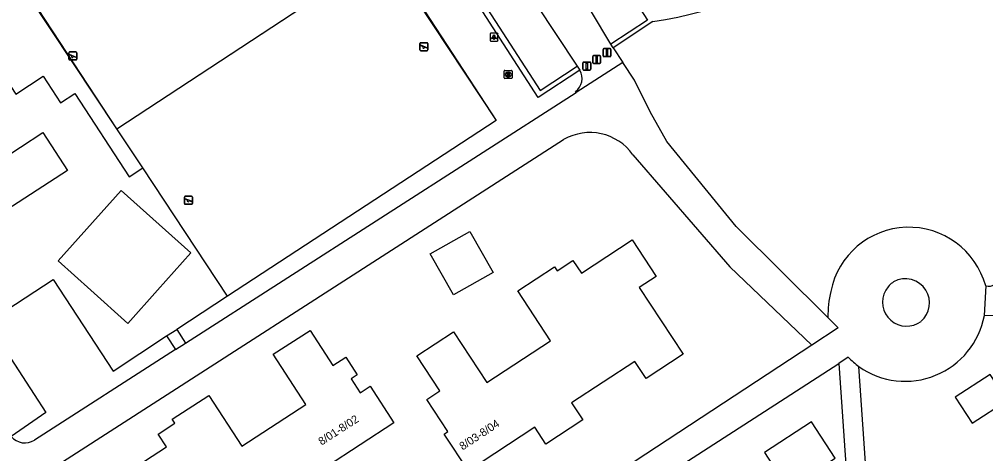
# Model space of a CAD drawing. Extents: x 159451 to 160663, y 388402 to 389723.
# Drawn here: x 159974 to 160094.7, y 389229.6 to 389283.8 of the extents above; entities that cross this region are included whole.
import ezdxf

# ---------------------------------------------------------------- set-up
doc = ezdxf.new("R2010")
doc.units = 0
for name, color, linetype in [('IMGEO_Afsluitpaal', 7, 'Continuous'), ('IMGEO_Groenvoorziening', 7, 'Continuous'), ('IMGEO_Haag', 7, 'Continuous'), ('IMGEO_Hek', 7, 'Continuous'), ('IMGEO_Lichtpunt', 7, 'Continuous'), ('IMGEO_Open_loods', 7, 'Continuous'), ('IMGEO_Pand', 7, 'Continuous'), ('IMGEO_Pand_nummerreeks', 7, 'Continuous'), ('IMGEO_Parkeervlak_open', 7, 'Continuous'), ('IMGEO_Rijbaan_lokaal_gesloten', 7, 'Continuous'), ('IMGEO_Rijbaan_lokaal_open', 7, 'Continuous'), ('IMGEO_Rioolput', 7, 'Continuous'), ('IMGEO_Speelvoorziening', 7, 'Continuous'), ('IMGEO_Voetpad_gesloten', 7, 'Continuous'), ('IMGEO_Voetpad_open', 7, 'Continuous')]:
    doc.layers.add(name, color=color, linetype=linetype)

msp = doc.modelspace()

# ---------------------------------------------------------------- linework, layer by layer
at = {"layer": 'IMGEO_Afsluitpaal'}
for p, q in [((160046.91, 389279.29), (160046.91, 389280.09)), ((160046.91, 389280.09), (160046.91, 389279.29)), ((160047.01, 389280.19), (160047.8, 389280.19)), ((160047.8, 389280.19), (160047.01, 389280.19)), ((160047.9, 389280.09), (160047.9, 389279.29)), ((160047.9, 389279.29), (160047.9, 389280.09)), ((160044.39, 389277.61), (160044.39, 389278.41)), ((160044.39, 389278.41), (160044.39, 389277.61)), ((160044.49, 389278.51), (160045.28, 389278.51)), ((160045.28, 389278.51), (160044.49, 389278.51)), ((160045.38, 389278.41), (160045.38, 389277.61)), ((160045.38, 389277.61), (160045.38, 389278.41)), ((160045.62, 389278.43), (160045.62, 389279.22)), ((160045.62, 389279.22), (160045.62, 389278.43)), ((160045.72, 389279.32), (160046.51, 389279.32)), ((160046.51, 389279.32), (160045.72, 389279.32)), ((160046.51, 389278.33), (160045.72, 389278.33)), ((160045.72, 389278.33), (160046.51, 389278.33)), ((160046.61, 389279.22), (160046.61, 389278.43)), ((160046.61, 389278.43), (160046.61, 389279.22)), ((160047.8, 389279.19), (160047.01, 389279.19)), ((160047.01, 389279.19), (160047.8, 389279.19)), ((160045.28, 389277.51), (160044.49, 389277.51)), ((160044.49, 389277.51), (160045.28, 389277.51))]:
    msp.add_line(p, q, dxfattribs=at)
for points in [[(160047.33, 389280.06), (160047.48, 389280.06), (160047.48, 389279.31), (160047.33, 389279.31), (160047.33, 389280.06)], [(160044.81, 389278.38), (160044.96, 389278.38), (160044.96, 389277.63), (160044.81, 389277.63), (160044.81, 389278.38)], [(160046.04, 389279.2), (160046.19, 389279.2), (160046.19, 389278.45), (160046.04, 389278.45), (160046.04, 389279.2)]]:
    msp.add_lwpolyline(points, dxfattribs=at)
for centre, start, end in [((160047.01, 389280.09), 90, 180), ((160047.01, 389280.09), 90, 180), ((160047.8, 389280.09), 0, 90), ((160047.8, 389280.09), 360, 90), ((160044.49, 389278.41), 90, 180), ((160044.49, 389278.41), 90, 180), ((160045.28, 389278.41), 0, 90), ((160045.28, 389278.41), 360, 90), ((160045.72, 389279.22), 90, 180), ((160045.72, 389279.22), 90, 180), ((160045.72, 389278.43), 180, 270), ((160045.72, 389278.43), 180, 270), ((160046.51, 389279.22), 0, 90), ((160046.51, 389279.22), 360, 90), ((160046.51, 389278.43), 270, 0), ((160046.51, 389278.43), 270, 0), ((160047.01, 389279.29), 180, 270), ((160047.01, 389279.29), 180, 270), ((160047.8, 389279.29), 270, 0), ((160047.8, 389279.29), 270, 0), ((160044.49, 389277.61), 180, 270), ((160044.49, 389277.61), 180, 270), ((160045.28, 389277.61), 270, 0), ((160045.28, 389277.61), 270, 0)]:
    msp.add_arc(centre, 0.1, start, end, dxfattribs=at)
at = {"layer": 'IMGEO_Groenvoorziening'}
for points in [[(159986.18, 389270.18), (159974.59, 389287.89), (160008.08, 389309.69), (160019.69, 389292.19)], [(159986.18, 389270.18), (160019.69, 389292.19)], [(160019.69, 389292.19), (160033.58, 389271.21), (160000.03, 389249.27)], [(159989.42, 389265.29), (159986.18, 389270.18)], [(160090.89, 389236.66), (160093.01, 389233.4), (160097.37, 389236.23), (160095.26, 389239.49), (160090.89, 389236.66)], [(160070.01, 389225.22), (160075.89, 389229.04), (160072.95, 389233.56), (160067.07, 389229.74), (160070.01, 389225.22)]]:
    msp.add_lwpolyline(points, dxfattribs=at)
at = {"layer": 'IMGEO_Haag'}
for points in [[(160044.02, 389277.48), (160038.8, 389274.1), (160012.9, 389314.21), (160017.65, 389317.31)], [(160053.14, 389283.56), (160048.18, 389280.3)]]:
    msp.add_lwpolyline(points, dxfattribs=at)
msp.add_arc((160045.07, 389336.91), 53.95, 278.6038, 331.4356, dxfattribs=at)
at = {"layer": 'IMGEO_Hek'}
for points in [[(159986.18, 389270.18), (159975.2, 389286.77), (160008.96, 389308.85), (160019.81, 389292.27)], [(159986.18, 389270.18), (160019.81, 389292.27)], [(160019.81, 389292.27), (160033.58, 389271.21), (160000.03, 389249.27)], [(159989.42, 389265.29), (159986.18, 389270.18)], [(160000.03, 389249.27), (159989.42, 389265.29)]]:
    msp.add_lwpolyline(points, dxfattribs=at)
at = {"layer": 'IMGEO_Lichtpunt'}
for p, q in [((160032.8, 389282.03), (160032.8, 389281.22)), ((160032.8, 389282.03), (160032.8, 389281.22)), ((160033.7, 389282.12), (160032.89, 389282.12)), ((160033.7, 389282.12), (160032.89, 389282.12)), ((160033.79, 389281.22), (160033.79, 389282.03)), ((160033.79, 389281.22), (160033.79, 389282.03)), ((160032.89, 389281.13), (160033.7, 389281.13)), ((160032.89, 389281.13), (160033.7, 389281.13))]:
    msp.add_line(p, q, dxfattribs=at)
for points in [[(160033.17, 389281.69), (160033.21, 389281.67), (160033.02, 389281.4), (160032.98, 389281.43), (160033.17, 389281.69)], [(160033.27, 389281.65), (160033.32, 389281.65), (160033.32, 389281.32), (160033.27, 389281.32), (160033.27, 389281.65)], [(160033.38, 389281.67), (160033.42, 389281.69), (160033.61, 389281.43), (160033.57, 389281.4), (160033.38, 389281.67)]]:
    msp.add_lwpolyline(points, dxfattribs=at)
msp.add_circle((160033.3, 389281.83), 0.0994, dxfattribs=at)
for centre, start, end in [((160032.89, 389282.03), 90, 180), ((160032.89, 389282.03), 90, 180), ((160033.7, 389282.03), 0, 90), ((160033.7, 389282.03), 0, 90), ((160032.89, 389281.22), 180, 270), ((160032.89, 389281.22), 180, 270), ((160033.7, 389281.22), 270, 0), ((160033.7, 389281.22), 270, 360)]:
    msp.add_arc(centre, 0.0946, start, end, dxfattribs=at)
at = {"layer": 'IMGEO_Open_loods'}
msp.add_lwpolyline([(159986.73, 389262.47), (159995.45, 389254.67), (159991.27, 389250), (159987.58, 389245.86), (159982.95, 389250), (159978.86, 389253.66), (159986.73, 389262.47)], dxfattribs=at)
at = {"layer": 'IMGEO_Pand'}
for points in [[(159968.55, 389264.2), (159976.93, 389269.69), (159980.01, 389264.98), (159971.62, 389259.5)], [(160028.25, 389249.43), (160025.34, 389254.56), (160030.26, 389257.35), (160033.17, 389252.23), (160028.25, 389249.43)], [(160051.44, 389250.36), (160056.92, 389242.01), (160052.29, 389238.96), (160050.87, 389241.12), (160042.98, 389235.94), (160044.38, 389233.81), (160039.78, 389230.79), (160038.4, 389232.89), (160030.09, 389227.43), (160027.07, 389232.03), (160027.53, 389232.34), (160024.89, 389236.34), (160026.55, 389237.42), (160023.67, 389241.8), (160028.24, 389244.79), (160032.39, 389238.47), (160040.35, 389243.69), (160036.26, 389249.91), (160040.87, 389252.94), (160041.2, 389252.44), (160043.16, 389253.73), (160044.21, 389252.13), (160050.55, 389256.29), (160053.54, 389251.73), (160051.44, 389250.36)], [(159986.07, 389226.32), (159992.41, 389230.43), (159991.37, 389232.03), (159993.45, 389233.38), (159993.11, 389233.9), (159997.69, 389236.87), (160001.8, 389230.53), (160009.8, 389235.72), (160005.72, 389242.01), (160010.32, 389244.99), (160013.16, 389240.62), (160014.77, 389241.66), (160016.22, 389239.43), (160015.44, 389238.93), (160016.56, 389237.2), (160017.81, 389238.01), (160020.79, 389233.42), (160012.36, 389227.95)]]:
    msp.add_lwpolyline(points, dxfattribs=at)
at = {"layer": 'IMGEO_Parkeervlak_open'}
for points in [[(160017.94, 389316.86), (160013.73, 389314.09), (160039.05, 389274.95), (160043.7, 389278)], [(160044.94, 389295.4), (160052.48, 389283.74), (160047.89, 389280.74)], [(159969.99, 389245.96), (159977.33, 389234.74), (159973, 389231.74)]]:
    msp.add_lwpolyline(points, dxfattribs=at)
at = {"layer": 'IMGEO_Rijbaan_lokaal_gesloten'}
for points in [[(160049.4, 389278.45), (160043.54, 389274.71)], [(160075, 389246.59), (160063.52, 389257.98), (160054.86, 389268.6), (160052.78, 389272.29), (160050.84, 389276.24), (160049.4, 389278.45)], [(159994.77, 389243.39), (160043.54, 389274.71)], [(159966.74, 389220.55), (159969.19, 389222.03), (160041.99, 389268.82)], [(160050.65, 389266.93), (160062.76, 389252.92), (160072.99, 389243.15)], [(160075, 389246.59), (160076.29, 389245.32), (160072.99, 389243.15)], [(159993.51, 389242.58), (159994.77, 389243.39)], [(159993.51, 389242.58), (159975.92, 389231.28)]]:
    msp.add_lwpolyline(points, dxfattribs=at)
for centre, radius, start, end in [((160045.28, 389263.1), 6.6, 35.5165, 119.9336), ((159974.72, 389233.15), 2.22, 219.254, 302.7061)]:
    msp.add_arc(centre, radius, start, end, dxfattribs=at)
at = {"layer": 'IMGEO_Rijbaan_lokaal_open'}
for points in [[(160017.94, 389316.86), (160043.7, 389278)], [(160047.89, 389280.74), (160040.78, 389292.71)], [(160048.18, 389280.3), (160047.89, 389280.74)], [(160048.18, 389280.3), (160049.4, 389278.45)], [(160043.7, 389278), (160044.02, 389277.48)], [(160043.54, 389274.71), (160043.47, 389274.82)], [(160094.7, 389250.55), (160094.53, 389246.84)], [(160072.99, 389243.15), (160034.2, 389217.64)], [(160036.5, 389215.12), (160068.36, 389235.7), (160076.35, 389240.87)], [(160077.54, 389241.64), (160076.35, 389240.87)]]:
    msp.add_lwpolyline(points, dxfattribs=at)
for centre, radius, start, end in [((160042.22, 389276.47), 2.07, 307.309, 29.2525), ((160085.11, 389247.93), 9.94, 15.2828, 168.82), ((160084.86, 389248.51), 3.03, 123.2192, 150.5671), ((160084.67, 389248.41), 3.02, 31.7007, 119.2412), ((160088.89, 389246.76), 13.89, 167.1286, 180.711), ((160084.84, 389248.52), 3.01, 150.605, 306.9536), ((160084.63, 389248.41), 3.05, 311.2675, 31.4443), ((160084.66, 389248.67), 10.04, 234.7811, 349.539), ((160083.57, 389247.19), 8.2, 222.6199, 235.0508)]:
    msp.add_arc(centre, radius, start, end, dxfattribs=at)
at = {"layer": 'IMGEO_Rioolput'}
for p, q in [((160034.56, 389276.53), (160034.56, 389277.38)), ((160034.63, 389277.45), (160035.49, 389277.45)), ((160035.05, 389277.23), (160035.07, 389277.23)), ((160035.56, 389277.38), (160035.56, 389276.53)), ((160035.49, 389276.45), (160034.63, 389276.45)), ((160035.07, 389276.67), (160035.04, 389276.67))]:
    msp.add_line(p, q, dxfattribs=at)
for points in [[(160034.56, 389276.53), (160034.56, 389277.38)], [(160034.63, 389277.45), (160035.49, 389277.45)], [(160035.15, 389277.15), (160034.89, 389277.15), (160034.89, 389276.75)], [(160035.07, 389277.07), (160035.02, 389277.07), (160035.02, 389276.99)], [(160035.56, 389277.38), (160035.56, 389276.53)], [(160035.49, 389276.45), (160034.63, 389276.45)], [(160034.89, 389276.75), (160035.02, 389276.75), (160035.02, 389276.92), (160035.03, 389276.92)], [(160035.02, 389276.99), (160035.07, 389276.99)], [(160035.08, 389276.89), (160035.15, 389276.75), (160035.29, 389276.75), (160035.22, 389276.88)]]:
    msp.add_lwpolyline(points, dxfattribs=at)
for centre, radius, start, end in [((160034.63, 389277.38), 0.0765, 91.552, 178.448), ((160034.63, 389277.38), 0.0765, 91.552, 178.448), ((160035.08, 389276.98), 0.0964, 77.0061, 93.1865), ((160035.09, 389277.03), 0.0378, 276.6634, 79.6772), ((160035.15, 389277.04), 0.109, 350.3612, 89.416), ((160035.48, 389277.38), 0.0765, 1.552, 88.448), ((160035.48, 389277.38), 0.0765, 1.552, 88.448), ((160034.63, 389276.53), 0.0765, 181.552, 268.448), ((160034.63, 389276.53), 0.0765, 181.552, 268.448), ((160035.03, 389276.86), 0.0533, 26.0293, 88.6989), ((160035.06, 389277.18), 0.19, 274.7715, 282.9687), ((160035.14, 389277.04), 0.112, 277.5842, 350.9817), ((160035.13, 389276.83), 0.108, 29.5134, 73.7905), ((160035.48, 389276.53), 0.0765, 271.552, 358.448), ((160035.48, 389276.53), 0.0765, 271.552, 358.448)]:
    msp.add_arc(centre, radius, start, end, dxfattribs=at)
for centre, major_axis, ratio, start_param, end_param in [((160035.05, 389276.95), (-0.387, 0.002), 0.722429, 4.712389, 7.853982), ((160035.07, 389276.95), (-0.39, 0.002), 0.717154, 1.570796, 4.712389)]:
    msp.add_ellipse(centre, major_axis=major_axis, ratio=ratio, start_param=start_param, end_param=end_param, dxfattribs=at)
at = {"layer": 'IMGEO_Speelvoorziening'}
for p, q in [((160024.04, 389280.02), (160024.04, 389280.82)), ((160024.04, 389280.82), (160024.04, 389280.02)), ((160024.14, 389280.92), (160024.93, 389280.92)), ((160024.93, 389280.92), (160024.14, 389280.92)), ((160025.03, 389280.82), (160025.03, 389280.02)), ((160025.03, 389280.02), (160025.03, 389280.82)), ((159980.19, 389278.87), (159980.19, 389279.67)), ((159980.19, 389279.67), (159980.19, 389278.87)), ((159980.25, 389279.49), (159981.13, 389279.14)), ((159980.29, 389279.77), (159981.08, 389279.77)), ((159981.08, 389279.77), (159980.29, 389279.77)), ((159981.18, 389279.67), (159981.18, 389278.87)), ((159981.18, 389278.87), (159981.18, 389279.67)), ((160024.42, 389280.45), (160024.08, 389280.58)), ((160024.11, 389280.65), (160024.98, 389280.29)), ((160024.93, 389279.92), (160024.14, 389279.92)), ((160024.14, 389279.92), (160024.93, 389279.92)), ((160024.96, 389280.23), (160024.62, 389280.37)), ((159980.57, 389279.3), (159980.23, 389279.43)), ((159981.08, 389278.77), (159980.29, 389278.77)), ((159980.29, 389278.77), (159981.08, 389278.77)), ((159981.11, 389279.08), (159980.77, 389279.22)), ((159994.63, 389260.84), (159994.63, 389261.64)), ((159994.63, 389261.64), (159994.63, 389260.84)), ((159995.01, 389261.27), (159994.68, 389261.41)), ((159994.7, 389261.47), (159995.58, 389261.12)), ((159994.73, 389261.74), (159995.52, 389261.74)), ((159995.52, 389261.74), (159994.73, 389261.74)), ((159995.62, 389261.64), (159995.62, 389260.84)), ((159995.62, 389260.84), (159995.62, 389261.64)), ((159995.52, 389260.74), (159994.73, 389260.74)), ((159994.73, 389260.74), (159995.52, 389260.74)), ((159995.55, 389261.05), (159995.21, 389261.19))]:
    msp.add_line(p, q, dxfattribs=at)
for centre, radius, start, end in [((160024.14, 389280.82), 0.1, 90, 180), ((160024.14, 389280.82), 0.1, 90, 180), ((160024.93, 389280.82), 0.1, 0, 90), ((160024.93, 389280.82), 0.1, 360, 90), ((159980.29, 389279.67), 0.1, 90, 180), ((159980.29, 389279.67), 0.1, 90, 180), ((159980.24, 389279.46), 0.0327, 68.078, 248.078), ((159981.08, 389279.67), 0.1, 0, 90), ((159981.08, 389279.67), 0.1, 360, 90), ((160024.14, 389280.02), 0.1, 180, 270), ((160024.14, 389280.02), 0.1, 180, 270), ((160024.09, 389280.61), 0.0327, 68.078, 248.078), ((160024.5, 389280.36), 0.12, 130.9928, 5.1632), ((160024.93, 389280.02), 0.1, 270, 0), ((160024.93, 389280.02), 0.1, 270, 0), ((160024.97, 389280.26), 0.0327, 248.078, 68.078), ((159980.29, 389278.87), 0.1, 180, 270), ((159980.29, 389278.87), 0.1, 180, 270), ((159980.65, 389279.21), 0.12, 130.9928, 5.1632), ((159981.08, 389278.87), 0.1, 270, 0), ((159981.08, 389278.87), 0.1, 270, 0), ((159981.12, 389279.11), 0.0327, 248.078, 68.078), ((159994.73, 389261.64), 0.1, 90, 180), ((159994.73, 389261.64), 0.1, 90, 180), ((159994.69, 389261.44), 0.0327, 68.078, 248.078), ((159995.52, 389261.64), 0.1, 0, 90), ((159995.52, 389261.64), 0.1, 360, 90), ((159994.73, 389260.84), 0.1, 180, 270), ((159994.73, 389260.84), 0.1, 180, 270), ((159995.09, 389261.18), 0.12, 130.9928, 5.1632), ((159995.52, 389260.84), 0.1, 270, 0), ((159995.52, 389260.84), 0.1, 270, 0), ((159995.56, 389261.09), 0.0327, 248.078, 68.078)]:
    msp.add_arc(centre, radius, start, end, dxfattribs=at)
at = {"layer": 'IMGEO_Voetpad_gesloten'}
for points in [[(160094.53, 389246.84), (160096.99, 389246.95)], [(160076.35, 389240.87), (160077.34, 389226.4)], [(160079.9, 389225.44), (160078.87, 389240.47)]]:
    msp.add_lwpolyline(points, dxfattribs=at)
msp.add_arc((160095.06, 389252.03), 1.52, 256.3148, 300.8302, dxfattribs=at)
at = {"layer": 'IMGEO_Voetpad_open'}
for points in [[(159964.99, 389287.63), (159973.59, 389274.49), (159977.01, 389276.73), (159979.17, 389273.42), (159980.94, 389274.58), (159987.74, 389264.19), (159989.42, 389265.29)], [(160000.03, 389249.27), (159989.42, 389265.29)], [(159969.99, 389245.96), (159978.23, 389251.35), (159985.72, 389239.91), (159992.41, 389244.29)], [(160000.03, 389249.27), (159993.67, 389245.11)], [(159992.41, 389244.29), (159993.67, 389245.11)], [(159993.67, 389245.11), (159994.77, 389243.39)], [(159992.41, 389244.29), (159993.51, 389242.58)]]:
    msp.add_lwpolyline(points, dxfattribs=at)

# ---------------------------------------------------------------- texts
at = {"layer": 'IMGEO_Pand_nummerreeks'}
for s, rotation, p in [('8/01-8/02', 32.8773, (160011.76, 389230.58)), ('8/03-8/04', 33.4838, (160029.38, 389229.97))]:
    msp.add_text(s, height=1, rotation=rotation, dxfattribs=at).set_placement(p)

doc.saveas('drawing.dxf')
